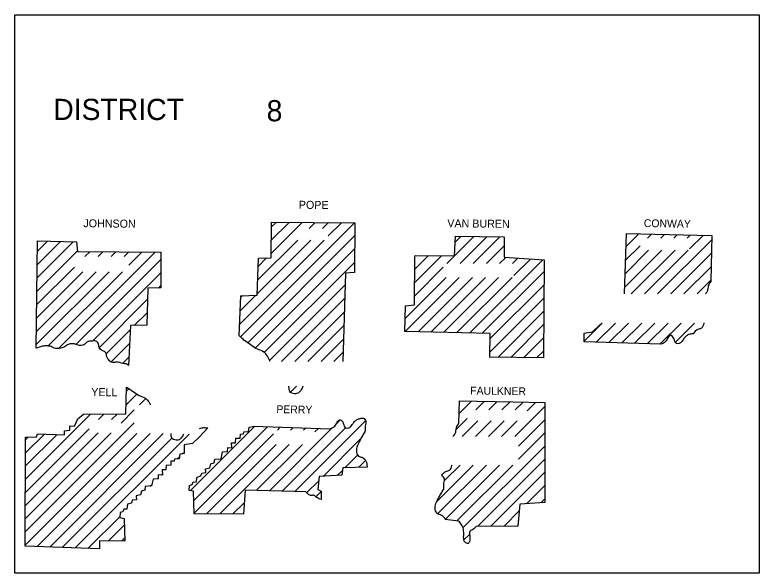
# Model space of a CAD drawing. Extents: x 21307 to 29830, y 1322443 to 1332359.
# Drawn here: x 27790.8 to 28190.8, y 1325699 to 1325999 of the extents above; entities that cross this region are included whole.
import ezdxf

# ---------------------------------------------------------------- set-up
doc = ezdxf.new("R2010")
doc.units = 0
doc.layers.add('R_Draft', color=7, linetype='Continuous')

msp = doc.modelspace()

# ---------------------------------------------------------------- linework, layer by layer
at = {"layer": 'R_Draft'}
msp.add_lwpolyline([(27790.76, 1325699.02), (27790.76, 1325999.02), (28190.76, 1325999.02), (28190.76, 1325699.02)], close=True, dxfattribs=at)
for points in [[(27911.26, 1325826.72), (27912.26, 1325848.12), (27921.06, 1325848.42), (27921.66, 1325868.32), (27928.56, 1325868.42), (27928.66, 1325887.62)], [(27912.06, 1325826.02), (27973.36, 1325887.32), (27973.36, 1325887.42)], [(27928.56, 1325870.82), (27945.16, 1325887.52)], [(27928.56, 1325877.92), (27938.16, 1325887.52)], [(27928.56, 1325885.02), (27931.16, 1325887.52)], [(27928.66, 1325887.62), (27973.46, 1325887.32)], [(27948.96, 1325884.22), (27952.16, 1325887.42)], [(27956.06, 1325884.22), (27959.26, 1325887.42)], [(27959.16, 1325880.22), (27966.26, 1325887.32)], [(27973.46, 1325887.32), (27973.26, 1325860.62), (27968.46, 1325860.22), (27966.96, 1325812.72)], [(27915.96, 1325822.82), (27973.36, 1325880.32)], [(28005.76, 1325869.72), (28027.06, 1325869.52), (28027.56, 1325880.02), (28053.36, 1325879.72)], [(28118.46, 1325849.02), (28119.46, 1325881.52)], [(28119.16, 1325874.42), (28126.06, 1325881.32)], [(28119.46, 1325881.52), (28165.36, 1325880.42), (28164.76, 1325855.72)], [(28130.86, 1325879.02), (28132.96, 1325881.12)], [(28137.86, 1325879.02), (28139.86, 1325881.02)], [(28144.96, 1325879.02), (28146.86, 1325880.92)], [(28152.06, 1325879.02), (28153.66, 1325880.62)], [(28153.36, 1325873.22), (28160.66, 1325880.52)], [(27802.16, 1325819.82), (27802.86, 1325877.62)], [(27802.56, 1325857.52), (27822.16, 1325877.12)], [(27802.66, 1325864.62), (27815.36, 1325877.32)], [(27802.76, 1325871.82), (27808.36, 1325877.42)], [(27802.86, 1325877.62), (27823.86, 1325877.12), (27824.36, 1325871.82)], [(27911.56, 1325832.62), (27956.96, 1325878.02)], [(27921.16, 1325849.32), (27949.86, 1325878.02)], [(27921.36, 1325856.62), (27942.76, 1325878.02)], [(28022.96, 1325865.42), (28027.06, 1325869.52), (28037.36, 1325879.92)], [(28027.36, 1325876.92), (28030.36, 1325879.92)], [(28030.06, 1325865.42), (28044.36, 1325879.82)], [(28037.06, 1325865.42), (28051.36, 1325879.72)], [(28053.66, 1325879.72), (28053.76, 1325868.82), (28075.16, 1325867.42), (28074.86, 1325814.72)], [(28136.16, 1325849.02), (28165.26, 1325878.12)], [(27802.56, 1325850.32), (27824.26, 1325872.12)], [(27920.16, 1325820.02), (27973.36, 1325873.22)], [(28044.16, 1325865.42), (28053.66, 1325874.92)], [(28118.56, 1325852.62), (28138.46, 1325872.52)], [(28118.76, 1325859.92), (28131.36, 1325872.52)], [(28118.96, 1325867.12), (28126.76, 1325874.92)], [(28122.06, 1325849.02), (28145.56, 1325872.52)], [(28129.16, 1325849.02), (28152.66, 1325872.52)], [(27814.36, 1325819.82), (27866.16, 1325871.52)], [(27824.36, 1325871.82), (27869.26, 1325871.52)], [(27828.36, 1325869.12), (27830.96, 1325871.72)], [(27835.46, 1325869.12), (27838.06, 1325871.72)], [(27842.56, 1325869.12), (27845.06, 1325871.62)], [(27849.56, 1325869.12), (27852.06, 1325871.62)], [(27869.26, 1325871.52), (27869.16, 1325852.32), (27862.26, 1325852.22), (27861.66, 1325832.32), (27852.86, 1325832.02), (27851.86, 1325810.62)], [(27852.06, 1325864.52), (27859.06, 1325871.52)], [(27921.46, 1325863.82), (27926.06, 1325868.42)], [(28000.36, 1325828.82), (28000.76, 1325842.72), (28005.56, 1325843.12), (28005.76, 1325869.12)], [(28005.66, 1325855.22), (28020.06, 1325869.52)], [(28005.76, 1325862.32), (28013.06, 1325869.72)], [(28005.76, 1325869.42), (28006.06, 1325869.72)], [(28051.26, 1325865.42), (28054.56, 1325868.72)], [(28058.26, 1325865.42), (28061.16, 1325868.32)], [(28143.26, 1325849.02), (28165.06, 1325870.82)], [(27823.66, 1325822.02), (27869.16, 1325867.52)], [(27924.86, 1325817.72), (27973.26, 1325866.02)], [(28035.06, 1325828.02), (28074.46, 1325867.42)], [(28058.86, 1325858.92), (28067.86, 1325867.82)], [(27802.26, 1325821.82), (27841.46, 1325861.02)], [(27802.36, 1325828.92), (27834.46, 1325861.02)], [(27802.36, 1325836.02), (27827.36, 1325861.02)], [(27802.46, 1325843.22), (27822.76, 1325863.52)], [(27808.56, 1325821.02), (27848.56, 1325861.02)], [(27832.46, 1325823.72), (27869.16, 1325860.42)], [(28005.66, 1325848.12), (28020.96, 1325863.42)], [(28041.96, 1325827.92), (28075.06, 1325861.02)], [(28150.36, 1325849.02), (28164.96, 1325863.62)], [(28000.46, 1325828.72), (28000.46, 1325828.82), (28029.56, 1325857.92)], [(28000.66, 1325836.02), (28022.56, 1325857.92)], [(28007.46, 1325828.72), (28036.66, 1325857.92)], [(28014.36, 1325828.52), (28043.76, 1325857.92)], [(28021.26, 1325828.42), (28050.76, 1325857.92)], [(28028.16, 1325828.22), (28057.96, 1325857.92)], [(28157.46, 1325849.02), (28164.76, 1325856.42)], [(27868.06, 1325852.22), (27869.16, 1325853.32)], [(27927.56, 1325813.32), (27968.26, 1325853.92)], [(28046.26, 1325825.12), (28075.06, 1325853.82)], [(27911.86, 1325840.02), (27920.26, 1325848.42)], [(27912.26, 1325847.42), (27913.06, 1325848.22)], [(27836.16, 1325820.32), (27862.06, 1325846.22)], [(27934.06, 1325812.72), (27968.06, 1325846.72)], [(28046.06, 1325817.82), (28075.06, 1325846.82)], [(27854.96, 1325832.02), (27861.86, 1325838.92)], [(27941.16, 1325812.72), (27967.76, 1325839.32)], [(28050.46, 1325815.12), (28074.96, 1325839.62)], [(27948.26, 1325812.72), (27967.56, 1325832.02)], [(28057.36, 1325814.92), (28074.96, 1325832.62)], [(28096.66, 1325823.32), (28096.66, 1325827.92), (28101.16, 1325828.62), (28105.06, 1325832.32), (28106.16, 1325833.42)], [(28096.66, 1325823.72), (28106.46, 1325833.42)], [(28103.26, 1325823.22), (28113.56, 1325833.42)], [(28110.06, 1325822.92), (28120.56, 1325833.42)], [(28116.96, 1325822.72), (28127.66, 1325833.42)], [(28123.76, 1325822.52), (28134.76, 1325833.42)], [(28130.66, 1325822.22), (28141.86, 1325833.42)], [(28137.46, 1325822.02), (28148.86, 1325833.42)], [(28145.76, 1325823.22), (28155.96, 1325833.42)], [(27839.96, 1325817.02), (27852.66, 1325829.72)], [(28045.96, 1325815.12), (28046.26, 1325827.72), (28000.56, 1325828.82)], [(27955.36, 1325812.72), (27967.36, 1325824.72)], [(28064.36, 1325814.92), (28074.86, 1325825.42)], [(27842.56, 1325812.62), (27852.46, 1325822.52)], [(28137.96, 1325822.02), (28096.76, 1325823.32)], [(27962.26, 1325812.72), (27967.06, 1325817.52)], [(28071.16, 1325814.72), (28074.86, 1325818.32)], [(27848.86, 1325811.82), (27852.06, 1325815.02)], [(28074.86, 1325814.72), (28045.76, 1325815.12)], [(27796.26, 1325713.52), (27796.46, 1325772.02), (27802.46, 1325772.22), (27802.96, 1325773.82), (27817.46, 1325773.42), (27817.36, 1325775.52), (27820.26, 1325775.82), (27820.36, 1325778.12), (27822.86, 1325777.92), (27824.56, 1325781.92), (27827.56, 1325784.52), (27850.36, 1325784.62), (27850.76, 1325799.02)], [(27850.76, 1325796.72), (27852.06, 1325798.02)], [(27938.86, 1325796.32), (27942.16, 1325799.52)], [(27850.46, 1325789.32), (27856.36, 1325795.22)], [(27857.76, 1325789.52), (27861.06, 1325792.82)], [(28029.36, 1325779.42), (28029.66, 1325791.52)], [(28029.46, 1325791.52), (28058.56, 1325791.12)], [(28029.46, 1325784.82), (28035.96, 1325791.32)], [(28038.46, 1325786.72), (28042.96, 1325791.32)], [(28058.56, 1325791.12), (28075.56, 1325790.62), (28075.56, 1325737.02), (28062.16, 1325736.02), (28061.16, 1325724.22), (28038.66, 1325724.12)], [(28045.46, 1325786.72), (28049.96, 1325791.22)], [(28052.56, 1325786.72), (28056.96, 1325791.12)], [(28059.46, 1325772.42), (28075.56, 1325788.52)], [(28059.66, 1325786.72), (28063.86, 1325790.92)], [(28066.16, 1325786.22), (28070.66, 1325790.72)], [(27796.46, 1325749.42), (27831.46, 1325784.52)], [(27835.66, 1325781.52), (27838.56, 1325784.52)], [(27842.66, 1325781.52), (27845.66, 1325784.52)], [(27847.86, 1325779.62), (27854.96, 1325786.72)], [(27941.16, 1325742.82), (27979.26, 1325780.82)], [(27963.56, 1325779.32), (27965.66, 1325781.42)], [(28027.96, 1325776.22), (28033.76, 1325782.12)], [(28031.16, 1325772.42), (28039.56, 1325780.82)], [(28038.26, 1325772.42), (28046.66, 1325780.82)], [(28045.36, 1325772.42), (28053.76, 1325780.82)], [(28052.36, 1325772.42), (28060.76, 1325780.82)], [(28061.36, 1325767.22), (28075.56, 1325781.42)], [(27796.36, 1325721.12), (27854.96, 1325779.72)], [(27796.46, 1325742.32), (27830.66, 1325776.62)], [(27894.46, 1325777.02), (27890.06, 1325772.32), (27886.16, 1325768.62), (27881.66, 1325767.92), (27881.66, 1325763.22), (27879.46, 1325762.92), (27879.06, 1325760.52), (27876.56, 1325760.32), (27876.36, 1325759.22), (27874.66, 1325759.12), (27874.56, 1325757.02), (27872.16, 1325756.92), (27871.96, 1325754.52), (27869.96, 1325754.52), (27870.06, 1325751.72), (27867.86, 1325751.92), (27867.76, 1325749.72), (27865.06, 1325749.52), (27864.26, 1325745.92), (27860.86, 1325745.62), (27860.56, 1325743.62), (27858.76, 1325743.12), (27858.26, 1325741.02), (27855.96, 1325740.52), (27856.16, 1325738.42), (27853.86, 1325738.22), (27853.46, 1325736.62), (27851.36, 1325736.02), (27850.86, 1325733.32), (27849.26, 1325733.42), (27848.76, 1325732.02), (27847.26, 1325731.52), (27847.16, 1325728.82), (27849.46, 1325728.42), (27849.86, 1325716.22)], [(27887.16, 1325730.82), (27886.76, 1325743.02), (27884.46, 1325743.42), (27884.56, 1325746.12), (27886.06, 1325746.62), (27886.56, 1325748.02), (27888.16, 1325747.92), (27888.66, 1325750.62), (27890.76, 1325751.22), (27891.16, 1325752.82), (27893.46, 1325753.02), (27893.26, 1325755.12), (27895.56, 1325755.62), (27896.06, 1325757.72), (27897.86, 1325758.22), (27898.16, 1325760.22), (27901.56, 1325760.52), (27902.36, 1325764.12), (27905.06, 1325764.32), (27905.16, 1325766.52), (27907.36, 1325766.32), (27907.26, 1325769.12), (27909.26, 1325769.12), (27909.46, 1325771.52), (27911.86, 1325771.62), (27911.96, 1325773.72), (27913.66, 1325773.82), (27913.86, 1325774.92), (27916.36, 1325775.12), (27916.76, 1325777.52), (27918.96, 1325777.82), (27918.96, 1325777.92)], [(27885.06, 1325743.32), (27919.66, 1325777.92)], [(27886.96, 1325738.12), (27926.56, 1325777.62)], [(27919.06, 1325777.92), (27960.26, 1325776.62)], [(27927.56, 1325743.32), (27960.96, 1325776.72)], [(27931.86, 1325775.92), (27933.36, 1325777.42)], [(27934.36, 1325743.02), (27968.46, 1325777.12)], [(27938.96, 1325775.92), (27940.26, 1325777.22)], [(27945.96, 1325775.92), (27947.06, 1325777.02)], [(27952.06, 1325774.92), (27953.86, 1325776.72)], [(27796.36, 1325728.12), (27842.56, 1325774.32)], [(27796.36, 1325714.02), (27856.36, 1325774.02)], [(27796.46, 1325735.32), (27835.46, 1325774.32)], [(27796.46, 1325763.62), (27806.66, 1325773.72)], [(27796.46, 1325756.62), (27813.46, 1325773.52)], [(27796.46, 1325770.72), (27797.86, 1325772.02)], [(27802.76, 1325713.32), (27863.46, 1325774.02)], [(27809.46, 1325713.02), (27870.46, 1325774.02)], [(27823.16, 1325712.52), (27884.36, 1325773.72)], [(27887.16, 1325731.22), (27929.76, 1325773.82)], [(28061.36, 1325760.22), (28075.56, 1325774.42)], [(27816.26, 1325712.72), (27875.16, 1325771.62)], [(27893.76, 1325730.82), (27931.16, 1325768.12)], [(27900.86, 1325730.82), (27938.16, 1325768.12)], [(27920.66, 1325743.52), (27945.26, 1325768.12)], [(27956.46, 1325751.02), (27976.76, 1325771.32)], [(27880.76, 1325763.12), (27881.66, 1325763.92), (27881.86, 1325764.12)], [(28031.56, 1325723.32), (28075.56, 1325767.32)], [(27878.06, 1325760.42), (27879.26, 1325761.52)], [(27968.06, 1325755.52), (27974.96, 1325762.42)], [(28039.56, 1325724.22), (28075.56, 1325760.22)], [(27979.76, 1325758.72), (27980.06, 1325756.02), (27966.96, 1325755.52), (27966.56, 1325751.62), (27954.26, 1325750.92), (27953.56, 1325743.92), (27955.36, 1325743.02), (27955.36, 1325738.52)], [(27975.36, 1325755.72), (27979.26, 1325759.62)], [(28017.66, 1325737.72), (28037.06, 1325757.12)], [(28018.06, 1325731.02), (28044.16, 1325757.12)], [(28021.86, 1325749.02), (28030.06, 1325757.12)], [(28022.06, 1325727.92), (28051.26, 1325757.12)], [(28028.46, 1325727.22), (28058.36, 1325757.12)], [(27869.36, 1325751.72), (27870.06, 1325752.32)], [(27963.96, 1325751.42), (27966.76, 1325754.22)], [(28046.56, 1325724.22), (28075.56, 1325753.22)], [(27867.36, 1325749.62), (27867.66, 1325750.02)], [(27947.56, 1325742.12), (27954.06, 1325748.62)], [(27863.56, 1325745.82), (27864.46, 1325746.72)], [(28065.76, 1325736.32), (28075.56, 1325746.12)], [(27947.16, 1325742.62), (27914.46, 1325743.62), (27913.56, 1325730.72), (27887.16, 1325730.82)], [(27952.56, 1325740.02), (27955.36, 1325742.92)], [(27907.96, 1325730.82), (27914.06, 1325736.82)], [(28073.36, 1325736.82), (28075.56, 1325739.02)], [(28053.66, 1325724.22), (28061.86, 1325732.42)], [(27829.96, 1325712.22), (27847.26, 1325729.52)], [(27841.06, 1325716.32), (27849.56, 1325724.82)], [(28029.26, 1325727.02), (28022.06, 1325727.82)], [(28060.76, 1325724.22), (28061.26, 1325724.72)], [(27849.86, 1325716.22), (27836.26, 1325716.32), (27836.16, 1325712.02)], [(27848.16, 1325716.32), (27849.86, 1325718.02)], [(28032.26, 1325717.02), (28035.16, 1325719.82)], [(27836.16, 1325712.02), (27796.26, 1325713.52)]]:
    msp.add_lwpolyline(points, dxfattribs=at)
for points in [[(28164.76, 1325855.72), (28163.46, 1325853.42), (28162.86, 1325850.42), (28161.76, 1325849.02)], [(28161.16, 1325833.42), (28161.06, 1325833.12), (28159.76, 1325830.62), (28157.76, 1325829.92), (28155.26, 1325827.62)], [(27914.36, 1325823.82), (27912.46, 1325825.62), (27911.26, 1325826.72)], [(28155.26, 1325827.62), (28154.06, 1325827.52), (28152.46, 1325827.02), (28150.96, 1325825.82), (28149.76, 1325824.22), (28147.86, 1325822.42), (28146.36, 1325822.42), (28144.96, 1325825.02), (28143.36, 1325826.82), (28141.76, 1325825.52), (28140.46, 1325823.42), (28137.96, 1325822.02)], [(27851.86, 1325810.62), (27851.06, 1325811.22), (27848.86, 1325811.72), (27845.46, 1325812.42), (27843.26, 1325812.22), (27841.96, 1325812.82), (27841.06, 1325813.82), (27840.16, 1325815.32), (27839.66, 1325817.42), (27837.96, 1325818.52), (27836.06, 1325820.22), (27835.76, 1325822.02), (27834.26, 1325823.72), (27832.16, 1325823.72), (27829.76, 1325823.32), (27828.36, 1325822.02), (27825.96, 1325821.32), (27823.76, 1325821.92), (27821.66, 1325822.32), (27819.46, 1325821.92), (27817.46, 1325820.62), (27815.46, 1325819.92), (27812.76, 1325819.72), (27810.26, 1325820.72), (27807.86, 1325821.12), (27805.46, 1325820.92), (27802.16, 1325819.82)], [(27927.96, 1325812.72), (27926.46, 1325815.62), (27924.56, 1325817.82), (27921.16, 1325819.32), (27917.86, 1325821.42), (27914.36, 1325823.82)], [(27850.76, 1325799.02), (27854.26, 1325796.62), (27857.56, 1325794.52), (27860.96, 1325793.02), (27862.86, 1325790.82), (27863.56, 1325789.52)], [(27945.56, 1325799.52), (27944.56, 1325797.42), (27943.26, 1325795.92), (27940.96, 1325795.42), (27938.56, 1325796.62), (27938.06, 1325799.12), (27937.96, 1325799.52)], [(27960.26, 1325776.62), (27962.76, 1325778.02), (27964.06, 1325780.12), (27965.66, 1325781.42), (27967.26, 1325779.62), (27968.66, 1325777.02), (27970.16, 1325777.02), (27972.06, 1325778.82), (27973.26, 1325780.42), (27974.76, 1325781.62), (27976.36, 1325782.12), (27978.06, 1325782.32), (27979.36, 1325780.42), (27978.96, 1325777.42), (27978.96, 1325775.42), (27977.86, 1325773.32), (27976.66, 1325771.12), (27975.36, 1325768.62), (27974.36, 1325765.92), (27974.56, 1325763.32), (27975.96, 1325761.62), (27977.56, 1325761.12), (27979.76, 1325758.92)], [(27889.96, 1325776.72), (27892.36, 1325777.22), (27894.46, 1325777.02)], [(28026.06, 1325772.42), (28027.46, 1325774.12), (28028.06, 1325777.12), (28029.36, 1325779.42)], [(27874.56, 1325774.02), (27874.96, 1325771.82), (27877.36, 1325770.62), (27879.66, 1325771.12), (27880.96, 1325772.62), (27881.56, 1325773.72)], [(28020.16, 1325751.62), (28022.36, 1325753.62), (28024.36, 1325754.32), (28025.66, 1325756.82), (28025.76, 1325757.12)], [(28022.06, 1325728.02), (28019.86, 1325730.22), (28018.26, 1325730.72), (28016.86, 1325732.42), (28016.66, 1325735.02), (28017.66, 1325737.72), (28018.96, 1325740.22), (28020.16, 1325742.42), (28021.26, 1325744.52), (28021.26, 1325746.52), (28021.66, 1325749.52), (28020.16, 1325751.62)], [(27955.36, 1325738.52), (27952.76, 1325739.92), (27951.26, 1325740.82), (27949.66, 1325740.72), (27948.36, 1325741.52), (27947.16, 1325742.62)], [(28038.66, 1325724.12), (28036.86, 1325722.42), (28035.16, 1325721.22), (28035.16, 1325719.82), (28035.36, 1325717.42), (28034.36, 1325715.02), (28032.76, 1325715.62), (28031.96, 1325718.42), (28031.96, 1325721.82), (28030.96, 1325724.82), (28029.26, 1325727.02)]]:
    msp.add_spline(points, degree=3, dxfattribs=at)

# ---------------------------------------------------------------- texts
for s, p in [('DISTRICT', (27811.36, 1325942.52)), ('8', (27926.06, 1325941.82))]:
    msp.add_text(s, height=11.4, dxfattribs=at).set_placement(p)
for s, height, rotation, p in [('POPE', 4.301, 359.6155, (27943.36, 1325894.82)), ('JOHNSON', 4.301, 359.3514, (27827.56, 1325884.92)), ('VAN BUREN', 4.301, 359.3508, (28023.16, 1325884.92)), ('CONWAY', 4.199, 359.0371, (28128.76, 1325885.02)), ('YELL', 4.301, 359.1987, (27831.76, 1325794.22)), ('FAULKNER', 4.201, 359.2486, (28035.46, 1325795.02)), ('PERRY', 4.201, 359.0858, (27931.26, 1325785.02))]:
    msp.add_text(s, height=height, rotation=rotation, dxfattribs=at).set_placement(p)

doc.saveas('drawing.dxf')
